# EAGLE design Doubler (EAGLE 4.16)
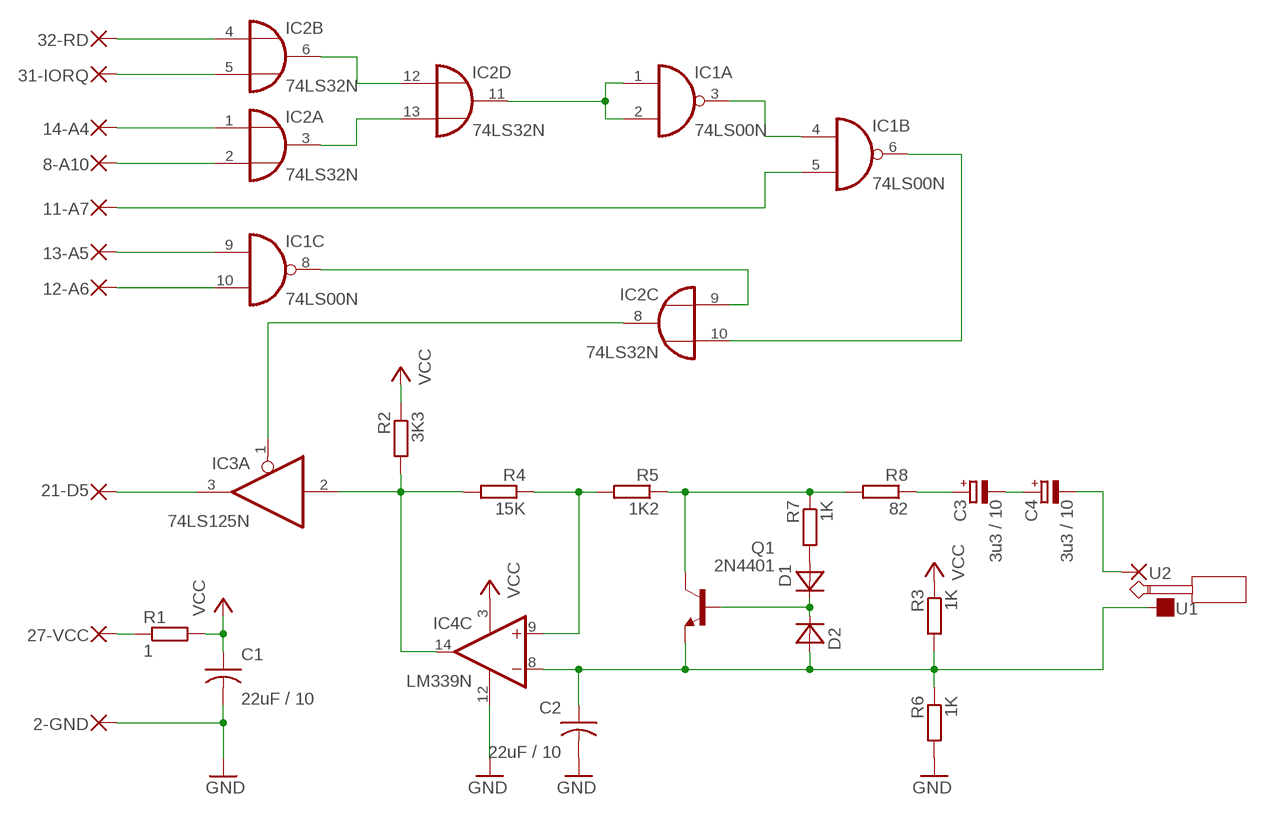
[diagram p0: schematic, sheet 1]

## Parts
2-GND  1,27-OVALADO0.8  [1,27/0,8]
8-A10  1,27-OVALADO0.8  [1,27/0,8]
11-A7  1,27-OVALADO0.8  [1,27/0,8]
12-A6  1,27-OVALADO0.8  [1,27/0,8]
13-A5  1,27-OVALADO0.8  [1,27/0,8]
14-A4  1,27-OVALADO0.8  [1,27/0,8]
21-D5  1,27-OVALADO0.8  [1,27/0,8]
27-VCC  1,27-REDONDO0.8  [1,27/0,8-REDONDO]
31-IORQ  1,27-OVALADO0.8  [1,27/0,8]
32-RD  1,27-OVALADO0.8  [1,27/0,8]
C1  22uF / 10  CAP-7,5  [C-7,5]
C2  22uF / 10  CAP-7,5  [C-7,5]
C3  3u3 / 10  CPOL-EUE5-4  [E5-4]
C4  3u3 / 10  CPOL-EUE5-4  [E5-4]
D1  DIODE-12,5/2  [D-12,5/2]
D2  DIODE-12,5/2  [D-12,5/2]
IC1  74LS00N  [DIL14]
IC2  74LS32N  [DIL14]
IC3  74LS125N  [DIL14]
IC4  LM339N  [DIL14]
Q1  2N4401  2N4416  [TO92]
R1  1  R-EU_0207/12  [0207/12]
R2  3K3  R-EU_0207/12  [0207/12]
R3  1K  R-EU_0207/12  [0207/12]
R4  15K  R-EU_0207/12  [0207/12]
R5  1K2  R-EU_0207/12  [0207/12]
R6  1K  R-EU_0207/12  [0207/12]
R7  1K  R-EU_0207/12  [0207/12]
R8  82  R-EU_0207/12  [0207/12]
U1  SMD1  [SMD1]
U2  SMD1  [SMD1]

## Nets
A4: 14-A4.1(P) IC2.1(A:I0)
A5: 13-A5.1(P) IC1.9(C:I0)
A6: 12-A6.1(P) IC1.10(C:I1)
A10: 8-A10.1(P) IC2.2(A:I1)
D5: 21-D5.1(P) IC3.3(A:O)
GND: 2-GND.1(P) C1.2 C2.2 IC4.12(P:GND) R6.2
IORQ: 31-IORQ.1(P) IC2.5(B:I1)
N$24: 11-A7.1(P) IC1.5(B:I1)
N$25: IC2.3(A:O) IC2.13(D:I1)
N$26: IC2.6(B:O) IC2.12(D:I0)
N$27: IC1.3(A:O) IC1.4(B:I0)
N$28: IC1.1(A:I0) IC1.2(A:I1) IC2.11(D:O)
N$30: IC1.6(B:O) IC2.10(C:I1)
N$31: IC1.8(C:O) IC2.9(C:I0)
N$32: IC2.8(C:O) IC3.1(A:OE)
N$53: 27-VCC.1(P) R1.1
N$58: IC3.2(A:I) IC4.14(C:OUT) R2.2 R4.2
N$62: IC4.9(C:+IN) R4.1 R5.2
N$63: C2.1 D2.P$1(A) IC4.8(C:-IN) Q1.3(E) R3.2 R6.1 U1.P$1(P)
N$64: Q1.1(C) R5.1 R7.1 R8.2
N$65: D1.P$1(A) R7.2
N$66: D1.P$2(K) D2.P$2(K) Q1.2(B)
N$68: C3.+ R8.1
N$69: C3.- C4.+
N$71: C4.- U2.P$1(P)
RD: 32-RD.1(P) IC2.4(B:I0)
VCC: C1.1 IC4.3(P:V+) R1.2 R2.1 R3.1
Unconnected: IC1.11(D:O) IC1.12(D:I0) IC1.13(D:I1) IC3.4(B:OE) IC3.5(B:I) IC3.6(B:O) IC3.8(C:O) IC3.9(C:I) IC3.10(C:OE) IC3.11(D:O) IC3.12(D:I) IC3.13(D:OE) IC4.1(B:OUT) IC4.2(A:OUT) IC4.4(A:-IN) IC4.5(A:+IN) IC4.6(B:-IN) IC4.7(B:+IN) IC4.10(D:-IN) IC4.11(D:+IN) IC4.13(D:OUT)

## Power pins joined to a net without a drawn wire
GND: IC1.7(P:GND) IC2.7(P:GND) IC3.7(P:GND)
VCC: IC1.14(P:VCC) IC2.14(P:VCC) IC3.14(P:VCC)

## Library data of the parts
2-GND 8-A10 11-A7 12-A6 13-A5 14-A4 21-D5 31-IORQ 32-RD = wirepad2:1,27-OVALADO
27-VCC = wirepad2:1,27-REDONDO
C1 C2 = discrete2:CAP-7,5
C3 C4 = rcl:CPOL-EU: POLARIZED CAPACITOR, European symbol
D1 D2 = discrete2:DIODE-12,5/2
IC1 = 74xx-eu:74*00: Quad 2-input NAND gate
IC2 = 74xx-eu:74*32: Quad 2-input OR gate
IC3 = 74xx-eu:74*125: Quad bus BUFFER, 3-state
IC4 = linear:LM339: Low Power Low Offset Voltage Quad Comparators with open collector; LM139/LM239/LM339/LM2901/LM3302
Q1 = transistor-npn:2N4416: NPN Transistor
R1-R8 = rcl:R-EU_: RESISTOR, European symbol
U1 U2 = wirepad2:SMD1

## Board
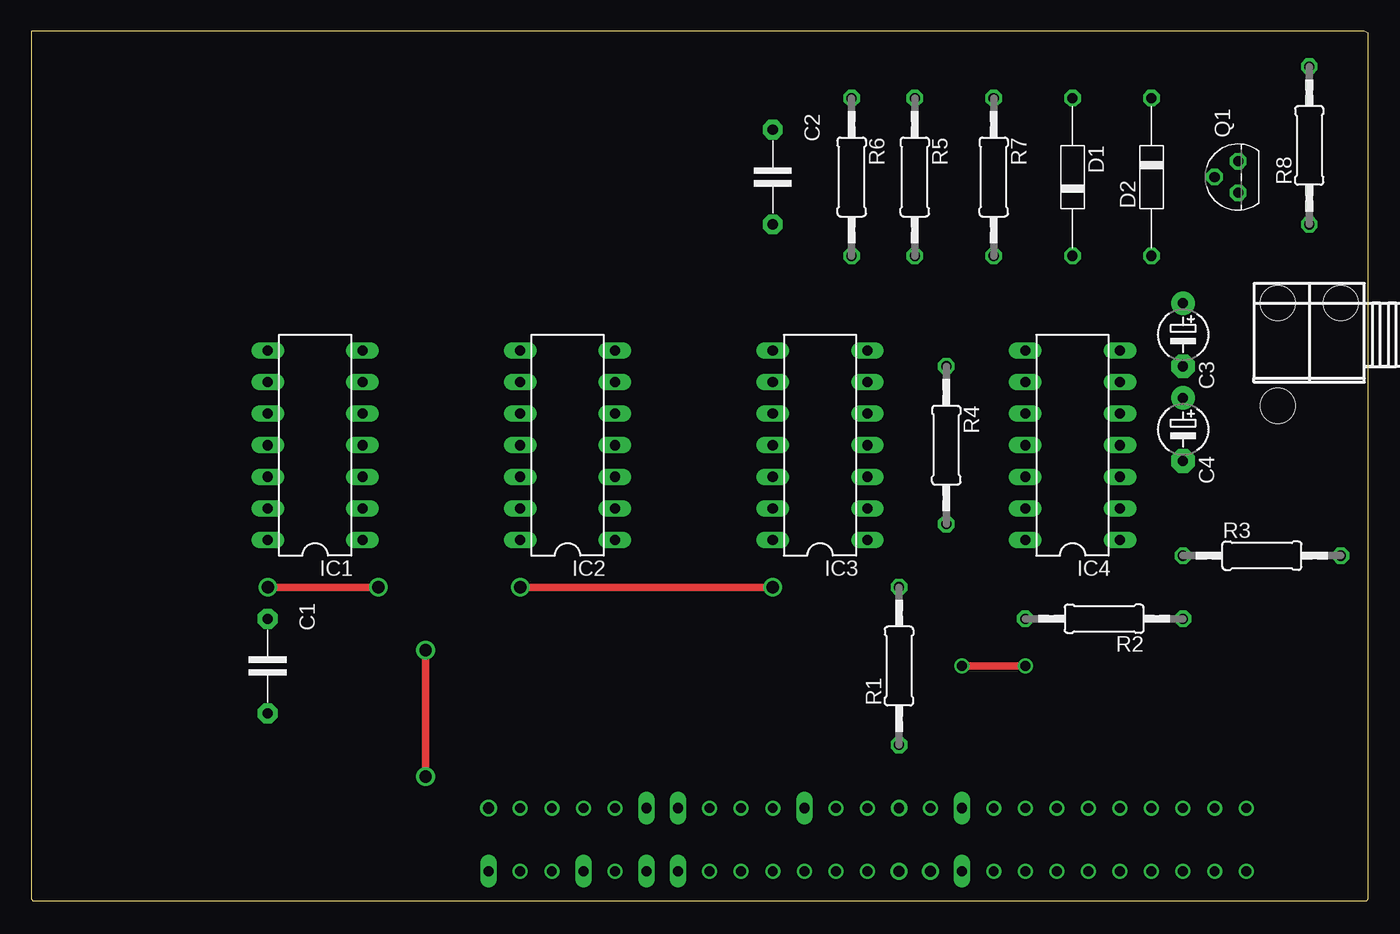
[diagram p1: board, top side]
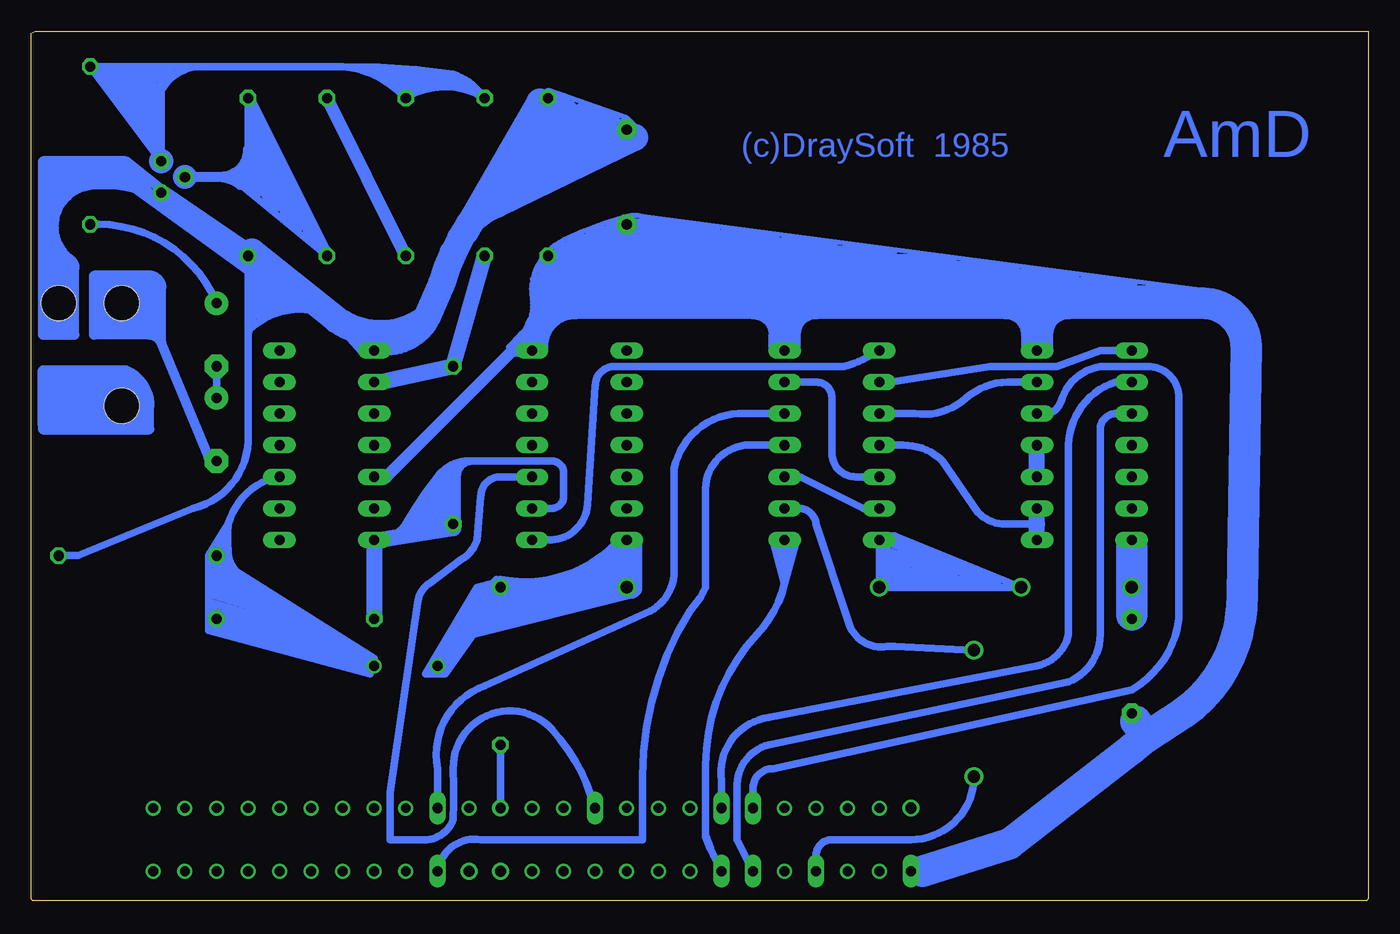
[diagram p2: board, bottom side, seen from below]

Size 107.63 x 70 mm. Coordinates in mm from the lower left corner, seen from the top.
Outline: 107.48,0 107.63,0.15 107.62,69.84 107.63,69.84 107.31,70 0,70 0,0.15 0.15,0 107.48,0
Copper layers (1*16): Top 0.035mm / dielectric 1.5mm / Bottom 0.035mm
Design rules "default": minimum track width 10mil, minimum drill 24mil, track to track 8mil, track to pad 8mil, pad to pad 8mil, via to via 8mil, smd to smd 8mil, copper to edge 40mil, drill to drill 8mil, minimum pad ring 10mil, minimum via ring 8mil, stop-mask expansion 4mil, vias tented up to drill 0mil, thermal gap 10mil
Holes 2.8 mm at 100.33,48.09 105.41,48.09 100.33,39.84

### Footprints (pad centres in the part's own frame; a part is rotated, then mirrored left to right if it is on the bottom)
1,27/0,8 = drill 0.813 long: 1 -1.27,1.27
1,27/0,8-REDONDO = drill 0.813 pad 1.27 round: 1 0,0
C-7,5 = drill 0.813 pad 1.6 octagon: 1 -3.81,0; 2 3.81,0
E5-4 = drill 0.813 pad 1.905 round: + -2.54,0 | drill 0.813 pad 1.905 octagon: - 2.54,0
D-12,5/2 = drill 0.813 octagon: P$1 -6.35,0; P$2 6.35,0
DIL14 = drill 0.813 long: 1 -7.62,-3.81; 2 -5.08,-3.81; 3 -2.54,-3.81; 4 0,-3.81; 5 2.54,-3.81; 6 5.08,-3.81; 7 7.62,-3.81; 8 7.62,3.81; 9 5.08,3.81; 10 2.54,3.81; 11 0,3.81; 12 -2.54,3.81; 13 -5.08,3.81; 14 -7.62,3.81
TO92 = drill 0.813 octagon: 1 1.27,0; 2 0,1.905; 3 -1.27,0
0207/12 = drill 0.813 octagon: 1 -6.35,0; 2 6.35,0
SMD1 = smd 0.635 x 1.27: P$1 0,0.635

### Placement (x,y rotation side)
2-GND  38.1,1.1 0 top
8-A10  45.72,1.1 0 top
11-A7  50.8,6.18 0 top
12-A6  50.8,1.1 0 top
13-A5  53.34,6.18 0 top
14-A4  53.34,1.1 0 top
21-D5  63.5,6.18 0 top
27-VCC  69.85,7.46 0 top
31-IORQ  76.2,6.18 0 top
32-RD  76.2,1.1 0 top
C1  19.05,18.89 270 top
C2  59.69,58.26 270 top
C3  92.71,45.55 270 top
C4  92.71,37.94 270 top
D1  83.82,58.26 270 top
D2  90.17,58.26 90 top
IC1  22.86,36.66 90 top
IC2  43.18,36.66 90 top
IC3  63.5,36.66 90 top
IC4  83.82,36.66 90 top
Q1  97.16,58.26 90 top
R1  69.85,18.89 90 top
R2  86.36,22.7 180 top
R3  99.06,27.78 0 top
R4  73.66,36.66 270 top
R5  71.12,58.26 270 top
R6  66.04,58.26 270 top
R7  77.47,58.26 270 top
R8  102.87,60.8 90 top
U1  105.41,48.09 90 bottom
U2  100.33,48.09 90 bottom

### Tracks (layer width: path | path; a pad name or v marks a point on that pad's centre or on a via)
A4
  Bottom 0.61: 14-A4.1 52.7,3.65 arc10 53.34,5.23 53.34,10.95 arc43 49.21,21.43 arc-29 46.99,25.55 | 46.99,25.55 47.94,29.05 47.62,29.05 | IC2.1 47.62,29.05 | IC2.1 46.35,29.05 | 46.35,29.05 46.04,29.05 46.99,25.55 | 46.99,25.55 46.99,26.51 | 46.99,26.51 IC2.1 | 46.99,26.51 47.62,29.05 | 47.62,29.05 46.35,29.05 | 46.99,26.51 46.35,29.05
A5
  Bottom 0.61: 13-A5.1 52.07,9.68 arc90 48.26,14.76 26.67,18.89 arc-64 24.13,21.43 24.13,36.66 arc72 20.32,41.74 IC1.9
A6
  Bottom 0.61: IC1.10 20.32,39.2 arc-90 21.59,37.94 21.59,21.43 arc67 24.13,17.62 48.26,12.54 arc-75 50.8,9.36 50.8,4.92 12-A6.1
A10  (via drill 1)
  Top 0.61: v31.75,10 v31.75,20.16
  Bottom 0.61: 8-A10.1 44.45,3.65 arc90 43.18,4.92 36.83,4.92 arc-90 v31.75,10 | v31.75,20.16 38.1,20.47 38.73,20.47 arc90 41.91,22.7 44.45,30.32 arc-90 46.04,31.59 IC2.2
D5
  Bottom 0.61: 21-D5.1 62.55,8.41 arc-24 65.72,13.81 arc-139 73.66,10.63 arc2 73.66,6.5 arc75 76.2,4.92 78.74,4.92 78.74,8.73 76.52,23.96 arc52 75.56,25.55 73.03,27.46 arc-45 71.75,29.05 71.44,32.54 arc90 69.85,34.12 IC3.3
GND
  Bottom 0.406: IC3.7 68.58,44.92 67.94,44.92 68.26,45.24 67.94,45.55 66.99,47.46 66.99,49.37 | 69.22,44.6 68.26,45.55 arc-53 67.31,48.41 arc72 64.77,53.18 arc10 59.69,55.08 arc31 58.42,55.08 12.7,49.05 17.14,49.37 66.67,49.37 | 66.99,49.37 67.31,49.37 67.31,49.68 18.73,49.68 21.59,50 67.31,50 66.99,50.32 23.5,50.32 26.35,50.63 66.04,50.63 | 66.04,50.63 66.67,50.63 66.67,50.95 28.26,50.95 31.11,51.27 66.67,51.27 66.36,51.59 33.34,51.59 36.2,51.91 R6.2 | R6.2 66.36,51.91 65.72,52.22 38.1,52.22 41.27,52.54 65.41,52.54 64.77,52.86 42.86,52.86 45.72,53.18 64.45,53.18 63.5,53.49 47.62,53.49 50.48,53.81 62.87,53.81 61.91,54.13 52.39,54.13 55.24,54.45 C2.2 | C2.2 61.28,54.45 60.31,54.69 | 60.31,54.69 60.01,54.76 57.15,54.76 | 66.99,49.37 66.67,49.37 | 66.67,49.37 66.67,48.73 | 60.31,54.69 60.33,54.76 C2.2 | 66.04,50.63 R6.2
  Bottom 1.016: IC4.12 79.06,34.12 68.9,44.29 IC3.7
  Bottom 1.27: 35.88,2.38 2-GND.1 | IC1.7 26.04,44.29 26.04,45.55 arc90 24.13,47.46 24.13,48.09 | IC1.7 27.3,44.29 27.3,45.55 arc-90 29.21,47.46 | 26.67,48.09 IC1.7 | IC2.7 46.35,44.29 46.35,45.55 arc90 44.45,47.46 44.45,48.09 | IC2.7 47.62,44.29 47.62,45.55 arc-90 49.53,47.46 46.99,47.46 IC2.7 | 63.82,48.09 63.82,47.46 arc-90 66.67,44.6 66.67,44.29 IC3.7 67.31,45.87 arc90 66.04,47.14 | 19.05,14.76 C1.2 18.73,14.44
  Bottom 2.54: 35.88,2.38 28.89,4.6 19.06,12.23 | 19.06,12.23 17.83,13.18 | 17.83,13.18 14.92,15.08 arc-56 10.16,24.6 9.84,44.6 arc-90 13.34,48.09 24.13,48.09 26.67,48.09 44.45,48.09 63.82,48.09 65.72,48.09 | 19.05,12.22 arc90 19.06,12.22 19.06,12.23 | 17.83,13.18 18.73,14.44
IORQ
  Bottom 0.61: IC2.5 50.16,39.2 arc-82 55.88,34.76 55.88,26.51 arc62 57.78,23.33 71.12,17.3 arc-81 74.93,10.63 31-IORQ.1
N$2  (via drill 0.9)
  other vias: 36.83,7.46
N$4  (via drill 0.8)
  other vias: 77.47,2.38
N$5  (via drill 0.8)
  other vias: 39.37,2.38
N$8  (via drill 0.8)
  other vias: 80.01,2.38
N$9  (via drill 0.8)
  other vias: 82.55,2.38
N$10  (via drill 0.8)
  other vias: 85.09,2.38
N$11  (via drill 0.8)
  other vias: 90.17,2.38
N$12  (via drill 0.8)
  other vias: 41.91,2.38
N$13  (via drill 0.8)
  other vias: 92.71,2.38
N$14  (via drill 0.8)
  other vias: 95.25,2.38
N$22  (via drill 0.8)
  other vias: 97.79,2.38
N$23  (via drill 0.8)
  other vias: 95.25,7.46
N$24
  Bottom 0.61: 11-A7.1 49.53,9.04 arc90 47.94,10.63 19.05,16.98 arc-52 15.24,22.7 15.24,40.48 arc-90 17.78,43.02 21.59,43.02 arc-64 24.77,40.16 arc74 26.04,39.2 IC1.5
N$25
  Bottom 0.61: IC2.13 40.64,31.59 45.72,34.12 IC2.3
N$26
  Bottom 0.61: IC2.6 44.45,41.74 arc90 43.18,40.48 43.18,36.03 arc-90 41.27,34.12 IC2.12
N$27
  Bottom 1.27: IC1.3 IC1.4
N$28
  Bottom 0.61: 26.67,30.32 29.21,30.32 arc46 31.43,31.27 34.29,35.4 arc-46 37.47,36.66 IC2.11
  Bottom 1.27: IC1.1 26.67,30.32 IC1.2
N$29  (via drill 0.8)
  other vias: 92.71,7.46
N$30
  Bottom 0.61: IC1.6 28.57,41.74 arc-44 32.38,40.48 arc50 36.51,39.2 IC2.10
N$31
  Bottom 0.61: IC2.9 38.42,41.74 30.48,43.02 25.08,43.02 21.59,44.29 IC1.8
N$32
  Bottom 0.61: IC2.8 39.69,44.29 arc32 42.23,43.02 60.64,43.02 arc-90 62.23,41.43 62.87,31.9 arc90 66.04,29.05 IC3.1
N$33  (via drill 0.8)
  other vias: 46.99,2.38
N$34  (via drill 0.8)
  other vias: 39.37,7.46
N$35  (via drill 0.8)
  other vias: 41.91,7.46
N$36  (via drill 0.8)
  other vias: 44.45,7.46
N$37  (via drill 0.8)
  other vias: 46.99,7.46
N$38  (via drill 0.8)
  other vias: 54.61,7.46
N$39  (via drill 0.8)
  other vias: 57.15,7.46
N$40  (via drill 0.8)
  other vias: 57.15,2.38
N$41  (via drill 0.8)
  other vias: 54.61,2.38
N$42  (via drill 0.8)
  other vias: 87.63,7.46
N$43  (via drill 0.8)
  other vias: 59.69,2.38
N$44  (via drill 0.8)
  other vias: 85.09,7.46
N$45  (via drill 0.8)
  other vias: 82.55,7.46
N$46  (via drill 0.8)
  other vias: 80.01,7.46
N$47  (via drill 0.8)
  other vias: 62.23,2.38
N$48  (via drill 0.8)
  other vias: 64.77,2.38
N$49  (via drill 0.8)
  other vias: 67.31,2.38
N$50  (via drill 0.8)
  other vias: 72.39,7.46
N$51  (via drill 0.9)
  other vias: 72.39,2.38
N$52  (via drill 0.9)
  other vias: 69.85,2.38
N$53
  Bottom 0.61: 27-VCC.1 R1.1
N$54  (via drill 0.8)
  other vias: 59.69,7.46
N$55  (via drill 0.8)
  other vias: 64.77,7.46
N$56  (via drill 0.8)
  other vias: 67.31,7.46
N$57  (via drill 0.8)
  other vias: 77.47,7.46
N$58
  Bottom 0.61: IC3.2 65.72,31.59 arc-90 64.77,32.54 64.77,34.44 arc-90 65.72,35.4 72.07,35.4 | 72.07,35.4 72.39,35.4 arc-53 74.93,34.12 arc-6 77.47,30.32 arc57 79.06,29.36 IC4.14 | 72.07,35.4 arc-90 73.34,34.12 74.3,34.12 74.3,30.32 74.61,30.32 74.61,34.12 74.93,33.49 74.93,30.32 75.25,30.32 75.25,33.17 75.56,32.54 75.56,30.32 75.88,30.32 75.88,32.22 76.2,31.59 76.2,30.32 76.52,30.32 76.52,31.27 76.83,30.63 76.83,30.32 77.47,29.68
  Bottom 1.27: R2.2 IC4.14 79.69,29.05 73.66,30 | 73.66,30 R4.2 | 73.66,30 73.66,34.44
N$59  (via drill 0.8)
  other vias: 97.79,7.46
N$60  (via drill 0.8)
  other vias: 90.17,7.46
N$61  (via drill 0.8)
  other vias: 87.63,2.38
N$62
  Bottom 1.27: IC4.9 79.38,41.74 R4.1 R5.2
N$63
  Bottom 0.406: 59.05,61.43 59.05,62.38 59.69,63.02 | 59.69,62.7 59.69,63.02 | 59.69,63.02 66.04,65.24 66.67,64.92 66.67,64.29 | 72.71,53.81 71.44,55.72 R6.1
  Bottom 0.61: R3.2 103.82,27.78 94.61,31.59 arc-75 90.17,36.98 90.17,45.55 arc53 89.85,46.19 arc6 88.9,46.83 arc61 83.19,46.83 83.5,47.14 | 90.17,50.63 90.17,45.87 | D2.P$1 90.17,51.27 | D2.P$1 85.09,47.78 86.04,47.78 89.85,50.95 89.85,50.32 87,48.09 86.68,47.78 87.31,47.78 89.85,49.68 89.85,49.05 87.95,47.78 88.58,47.46 89.85,48.41 89.85,47.78 88.9,47.14 89.85,47.14 89.85,46.51 | D2.P$1 97.47,56.67 97.47,56.35 90.17,51.27 | 90.17,51.27 90.17,50.63 | 90.17,50.63 99.38,57.3
  Bottom 0.813: 59.37,61.75 71.44,55.72 70.48,56.98 C2.1 59.69,62.7 69.85,57.94 68.9,58.89 60.64,63.02 61.59,63.34 68.9,59.52 68.26,60.8 62.55,63.65 | 62.55,63.65 61.91,63.34 | 62.55,63.65 63.18,63.97 67.63,61.75 66.99,62.7 64.14,63.97 64.77,64.29 66.67,63.02 65.41,64.6 | 65.41,64.6 64.77,64.6 | R6.1 65.41,64.6 | 75.88,46.83 75.71,47.09 75.25,46.51 arc61 79.06,44.29 IC4.8 80.96,44.29 83.5,47.14 81.6,45.55 76.83,45.55 75.88,45.87 78.11,44.92 81.28,45.24 80.96,44.92 79.69,44.6 | 106.68,48.09 U1.P$1 | 106.68,48.09 106.68,59.52 100.01,59.52 96.84,56.98 | 106.68,48.09 106.68,45.55 104.14,45.55 104.14,50.95 arc-53 104.46,51.59 arc136 102.87,57.62 arc24 99.06,57.3 arc19 97.79,56.67 99.06,57.94 | 99.06,57.94 100.33,59.21 106.05,59.21 106.05,45.87 105.73,45.87 105.73,52.22 105.09,51.59 105.09,45.87 104.78,45.87 104.78,51.27 106.36,54.45 105.41,56.35 105.41,56.98 | 105.41,57.94 105.41,56.98 | 105.41,58.26 105.41,58.89 100.33,58.89 100.01,58.57 105.41,58.26 | 105.41,57.94 105.41,58.26 | 99.06,57.94 105.41,57.94 | 99.06,57.94 104.46,57.62 105.41,56.98
  Bottom 1.016: Q1.3 96.84,56.98 89.85,52.22 D2.P$1
  Bottom 2.184: 75.71,47.09 74.61,49.68 arc17 72.39,54.45 arc34 70.17,56.03 59.05,61.43 | 72.71,53.81 66.67,64.29 | 89.85,52.22 83.5,47.14 arc-77 75.88,46.83
N$64
  Bottom 0.61: R7.1 arc59 71.75,64.92 R5.1 71.44,64.92 arc-40 73.66,66.51 arc-10 82.55,67.14 | R7.1 77.79,64.92 arc-40 82.55,67.14 | 82.55,67.14 93.98,67.14 | 93.98,67.14 94.3,67.14 arc-53 97.16,65.24 Q1.1 R8.2 | 93.98,67.14 R8.2 | R8.2 102.23,66.51 96.2,66.51 97.16,66.19 101.92,66.19 97.47,60.48 97.47,61.11 101.28,65.88 100.65,65.88 97.47,61.75 97.47,62.38 100.33,65.88 99.69,65.88 97.47,63.02 97.47,63.65 99.38,65.88 99.06,65.88 97.47,64.29 97.47,64.92 98.42,65.88 97.79,65.88 97.47,65.24 97.16,65.88 | 80.01,66.83 72.71,65.88 72.39,65.56 79.38,66.19 78.42,65.88 76.2,65.56 77.15,65.24 77.47,64.92 | 77.47,64.92 77.79,65.56 | 77.47,64.92 77.47,65.56 | R7.1 77.47,64.92
N$65
  Bottom 1.016: R7.2 D1.P$1
N$66
  Bottom 0.61: 92.71,58.26 92.39,58.26 | D2.P$2 90.17,60.48 | D1.P$2 90.81,57.62 90.81,58.26 90.49,58.57 90.17,57.3 89.22,56.98 90.49,58.89 90.17,59.21 88.58,56.35 87.95,55.72 89.85,59.84 89.85,60.8 87,54.76 86.04,54.13 89.85,61.75 89.85,62.7 85.09,53.18
  Bottom 0.813: Q1.2 92.71,58.26 arc42 90.81,57.62 | 90.17,60.48 arc90 92.39,58.26
  Bottom 1.016: D1.P$2 D2.P$2
N$68
  Bottom 0.61: R8.1 102.23,54.45 arc67 C3.+
N$69
  Bottom 0.61: C4.+ C3.-
N$71
  Bottom 0.813: C4.- 93.34,35.71 97.16,44.92 | 97.16,44.92 arc-68 98.11,45.55 102.55,45.55 102.55,50.32 98.11,50.32 arc90 97.16,49.37 97.16,44.92 | 97.16,44.92 97.79,45.87 97.79,50 98.11,50 98.11,45.87 98.42,45.87 98.42,49.68 101.92,49.68 101.92,46.19 99.06,46.19 99.06,49.05 101.28,49.05 101.28,46.83 99.69,46.83 99.69,48.41 100.65,48.41 U2.P$1
N$72
  Bottom 0.813: 100.33,47.78 100.33,47.14 100.97,47.14 100.97,48.73
N$73
  Bottom 0.813: 106.68,38.25 106.68,42.7 100.01,42.7 arc67 98.11,39.84 98.11,37.94 106.68,37.94 106.68,38.25 | 106.68,38.25 98.74,38.25 98.74,38.89 106.05,38.89 106.05,39.52 98.42,39.52 98.42,40.16 106.36,40.16 106.36,40.79 98.74,40.79 99.38,41.43 106.36,41.43 106.36,42.06 99.69,42.06
RD
  Bottom 0.61: 32-RD.1 arc90 71.44,4.92 58.42,4.92 58.42,10 arc32 54.61,23.33 arc-20 53.34,25.23 53.34,33.17 arc82 50.16,36.66 IC2.4
VCC  (via drill 0.8, 1)
  Top 0.61: v19.05,25.23 v27.94,25.23 | v39.37,25.23 v59.69,25.23 | v74.93,18.89 v80.01,18.89
  Bottom 0.61: v19.05,25.23 IC1.14 | v59.69,25.23 IC3.14 | IC2.14 39.37,29.36 38.1,29.36 v27.94,25.23 v39.37,25.23 39.37,25.55 | 39.37,25.55 IC2.14 | 39.37,25.55 29.84,25.55 38.1,29.05 39.05,29.05 | 39.05,29.05 39.05,25.87 31.43,25.87 38.42,28.73 38.73,28.73 38.73,26.19 33.34,26.19 38.42,28.09 38.42,27.78 | 38.42,27.78 38.42,26.51 35.24,26.51 38.42,27.78 | 38.42,27.78 38.1,26.82 37.78,27.14 37.15,26.82 | IC2.14 39.05,29.05 | R1.2 69.85,25.87 arc-59 60.33,29.05 IC3.14 | IC3.14 59.05,29.05 | 59.05,29.05 58.74,29.05 58.74,25.23 arc90 59.37,24.6 72.07,21.43 74.3,18.25 | 74.3,18.25 75.88,18.25 71.75,25.23 70.48,25.55 70.17,25.87 70.17,25.55 60.96,25.55 | 59.05,29.05 59.05,24.92 59.69,24.6 v59.69,25.23 | v59.69,25.23 60.01,24.6 60.01,28.73 60.33,28.41 60.33,24.6 60.64,24.6 60.64,28.09 60.96,27.46 60.96,25.55 | 60.96,25.23 60.96,24.92 | 60.96,24.6 60.96,24.28 61.59,24.28 61.59,27.14 61.91,26.51 61.91,24.28 62.23,24.28 | v80.01,18.89 80.33,18.25 93.34,21.74 | 93.34,21.74 R2.1 | 93.34,21.74 93.34,22.06 | 93.34,22.38 93.34,27.78 | 93.34,27.78 91.76,30.32 | 91.76,30.32 arc64 IC4.3 | 93.34,27.78 R3.1 | 80.33,18.89 80.01,19.2 80.01,19.52 91.12,26.51 arc44 91.76,28.09 arc10 91.76,30.32 | 80.33,18.89 80.64,18.57 93.34,22.06 | 93.34,22.06 93.34,22.38 | 93.34,22.38 80.33,18.89 | 80.33,18.89 80.64,19.2 93.03,22.7 93.03,23.01 80.64,19.52 81.6,20.16 93.03,23.33 93.03,23.96 82.55,20.79 83.82,21.74 93.03,24.6 93.03,24.92 85.09,22.38 86.36,23.01 93.03,25.23 93.03,25.87 86.68,23.33 87.95,24.28 93.03,26.19 93.03,26.51 89.22,25.23 92.39,26.82 | 92.39,26.82 93.03,27.14 | 92.39,26.82 92.71,27.14 | 92.39,26.82 92.39,27.46
  Bottom 0.61: 91.76,30.32 92.71,28.09 92.39,27.78 91.76,26.82 92.39,28.41 92.08,29.05 | 74.3,18.25 v74.93,18.89 | 60.96,25.55 60.96,25.23 | 60.96,25.23 71.44,25.23 71.75,24.92 60.96,24.92 | 60.96,24.92 60.96,24.6 | 60.96,24.6 71.75,24.6 72.07,24.28 62.55,24.28 63.5,23.96 72.39,23.96 72.39,23.65 64.45,23.65 66.04,23.33 72.39,23.33 72.71,23.01 67.31,23.01 68.26,22.7 72.71,22.7 73.03,22.38 69.85,22.38 71.44,22.06 73.03,22.06 | 73.03,22.06 73.34,22.06 75.25,18.89 74.61,18.89 73.03,22.06 | 73.03,22.06 72.71,21.74 74.3,18.57 72.07,21.74 | v59.69,25.23 59.37,25.23 59.37,28.73 64.77,25.87 63.82,25.87 | 62.23,25.87 61.28,25.87 61.28,27.46 63.82,25.87 | 63.82,25.87 62.87,25.87 | 62.87,25.87 62.23,25.87 | 62.23,25.87 62.23,26.51 62.87,25.87
  Bottom 1.27: 19.05,28.41 IC1.14 | C1.1 19.05,23.01
  Bottom 2.54: 19.05,28.41 v19.05,25.23 19.05,23.01
(copper drawn outside any net)
  shapes: Bottom circle x2

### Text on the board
Bottom: AmD | (c)DraySoft 1985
